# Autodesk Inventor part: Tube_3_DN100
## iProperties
Shininess: 64.0
Length Units: 11269
Angle Units: 11279
Time Units: 11290
Mass Units: 11283
Length Display Precision: 3
Angle Display Precision: 2
Compacted: True
Part Number: Tube_3_DN100
Document SubType Name: Modeling
Created: 2008-04
Material: Par défaut
Designer: plup
Density: 0.0
Volumn: 0.0
Area: 0.0
PropertySet Name: Model Information
Control State: 0
Master: False
Checked Out: False
MATIERE_PIECE: X2CrNi 18-11
OBSERVATIONS: Lg.: .......
DESIGNATION: Tube 3
Author: plup
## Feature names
1. Extrusion1
